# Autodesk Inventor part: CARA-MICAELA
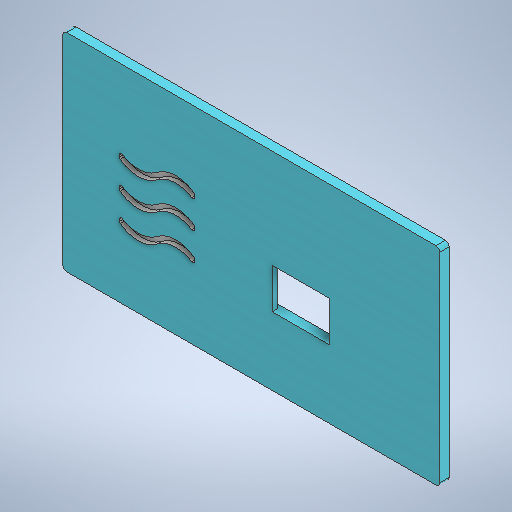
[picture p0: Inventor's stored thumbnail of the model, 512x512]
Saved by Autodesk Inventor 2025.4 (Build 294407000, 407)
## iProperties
Created: 2026-06
Part Number: CARA-MICAELA
Material: Generic
Document SubType Name: Modeling
Designer: Marcio Valenzuela
Density: 1 g/cm^3
Appearance: Default
Author: Marcio Valenzuela
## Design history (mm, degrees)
sketch "Sketch11"
  geometry: L1 (-200, 110)-(200, 110); L2 (200, 110)-(200, -110); L3 (200, -110)-(-200, -110); L4 (-200, -110)-(-200, 110); L5 (-200, 110)-(200, -110); L6 (200, 110)-(-200, -110); 1 further point
  constraints: 12 end point, 2 midpoint, 2 parallel, 1 horizontal, 1 perpendicular
  dimensions: "d50" = 400 distance of L2.end L3.end; "d51" = 220 distance of L1.end L2.end
extrude "Extrusion7" new body sketch "Sketch11" distance "d52" = 10; taper "d53" = 0 deg
fillet "Fillet2" dims "d54" = 4
sketch "Sketch12"
  geometry: L1 (82.569, -37.626)-(22.309, -37.626); L2 (22.309, -37.626)-(22.309, 5.094); L3 (22.309, 5.094)-(82.569, 5.094); L4 (82.569, 5.094)-(82.569, -37.626); L5 (82.569, -37.626)-(22.309, 5.094); L6 (22.309, -37.626)-(82.569, 5.094)
  constraints: 12 end point, 2 parallel, 1 horizontal, 1 perpendicular
  dimensions: "d57" = 60.26 distance of L2.end L3.end; "d58" = 42.72 distance of L1.end L2.end
extrude "Extrusion8" cut sketch "Sketch12" distance "d60" = 10; taper "d61" = 0 deg
sketch "Sketch13"
  geometry: L1 (-91.029, 5.094)-(-13.849, 5.094); L2 (-13.849, 5.094)-(-13.849, -37.626); L3 (-13.849, -37.626)-(-91.029, -37.626); L4 (-91.029, -37.626)-(-91.029, 5.094); L5 (-91.029, 5.094)-(-13.849, -37.626); L6 (-13.849, 5.094)-(-91.029, -37.626); 2 further points
  constraints: 12 end point, 2 midpoint, 2 parallel, 1 horizontal, 1 perpendicular
  dimensions: "d62" = 77.18 distance of L2.end L3.end; "d63" = 42.72 distance of L1.end L2.end
extrude "Extrusion9" cut sketch "Sketch13" distance "d64" = 5; taper "d65" = 0 deg
sketch "Sketch14"
  geometry: L1 (-200, 106)-(-200, -106) reference; L2 (-140, 29.5)-(-140, 22.5); L3 (-140, 0)-(-140, -7); L4 (-139.931, -29.555)-(-139.931, -36.555); L5 (-60, 29.5)-(-60, 22.5); L6 (-60, 0)-(-60, -7); L7 (-60, -29.5)-(-60, -36.5); A1 r 32.071 centre (-120, 54.571) between (-140, 29.5) and (-100, 29.5); A2 r 32.071 centre (-80, 4.429) between (-60, 29.5) and (-100, 29.5); A3 r 32.071 centre (-120, 25.071) between (-140, 0) and (-100, 0); A4 r 32.071 centre (-80, -25.071) between (-60, 0) and (-100, 0); A5 r 32.071 centre (-120, -4.429) between (-139.931, -29.555) and (-100, -29.5); A6 r 32.071 centre (-80, -54.571) between (-60, -29.5) and (-100, -29.5); A7 r 32.071 centre (-120, 47.571) between (-140, 22.5) and (-100, 22.5); A8 r 32.071 centre (-80, -2.571) between (-60, 22.5) and (-100, 22.5); A9 r 32.071 centre (-120, 18.071) between (-140, -7) and (-100, -7); A10 r 32.071 centre (-80, -32.071) between (-60, -7) and (-100, -7); A11 r 32.071 centre (-120, -11.429) between (-139.931, -36.555) and (-100, -36.5); A12 r 32.071 centre (-80, -61.571) between (-60, -36.5) and (-100, -36.5); 7 further points
  constraints: 30 point on circle, 12 centre point, 12 end point, 3 equal radius, 2 collinear, 2 vertical
  dimensions: "d73" = 7 distance of L2.start L2.end; "d74" = 7 distance of L3.start L3.end; "d76" = 7 distance of point (-120, 15.5) point (-120, 22.5); "d77" = 32.07143 radius of A1 (derived); "d78" = 32.071 radius of A9; "d80" = 7 distance of L4.start L4.end
extrude "Extrusion10" cut sketch "Sketch14" distance "d83" = 5; taper "d84" = 0 deg
fillet "Fillet3" dims "d85" = 2
feature "ƥ耀Ƨ耀Ʃ耀ƫ耀ƭ耀Ư耀Ʊ耀Ƴ耀" dims "d50" = 400, "d51" = 220, "d52" = 10, "d53" = 0, "d54" = 4, "d57" = 60.26, "d58" = 42.72, "d60" = 10, "d61" = 0, "d62" = 77.18, "d63" = 42.72, "d64" = 5, "d65" = 0, "d73" = 7, "d74" = 7, "d76" = 7, "d77" = 32.07143 (derived), "d78" = 32.071, "d80" = 7, "d83" = 5, "d84" = 0, "d85" = 2
body "Solid2"
